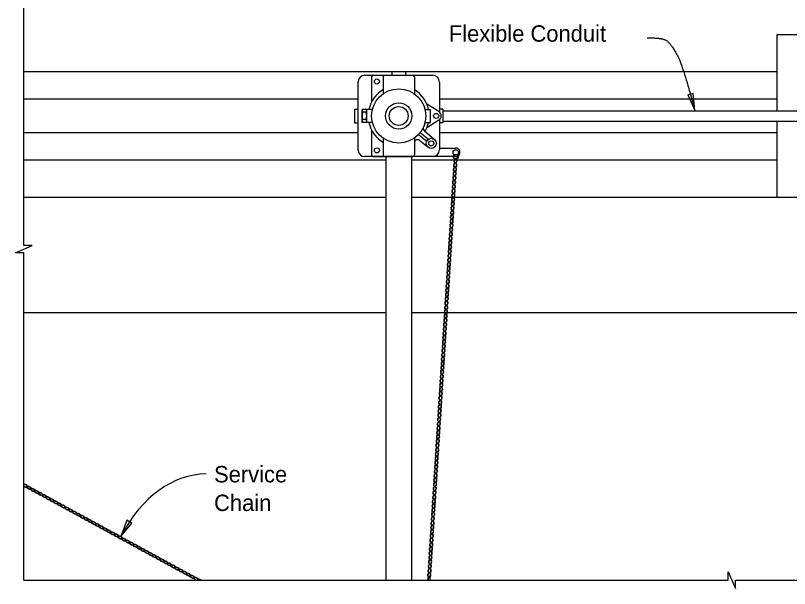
# Model space of a CAD drawing. Extents: x 83976.6 to 84012, y 72958.9 to 72975.6.
# Drawn here: x 83982.392 to 83987.152, y 72963.229 to 72966.752 of the extents above; entities that cross this region are included whole.
import ezdxf

# ---------------------------------------------------------------- set-up
doc = ezdxf.new("R2010")
doc.units = 0
for name, color, linetype in [('DSText', 7, 'Continuous'), ('DSTitle', 7, 'Continuous'), ('Patterning', 7, 'Continuous'), ('PlotBorder_dp', 7, 'Continuous'), ('SheetLines_dp', 7, 'Continuous'), ('SupstrConc', 7, 'Continuous')]:
    doc.layers.add(name, color=color, linetype=linetype)

msp = doc.modelspace()

# ---------------------------------------------------------------- linework, layer by layer
at = {"layer": 'DSText'}
for p, q in [((83984.7905, 72966.4049), (83984.7072, 72966.4049)), ((83984.7072, 72966.4049), (83984.7072, 72966.3841)), ((83984.7905, 72966.4049), (83984.7905, 72966.3841)), ((83984.5822, 72966.3737), (83984.5822, 72966.2199)), ((83984.5926, 72966.3841), (83984.8351, 72966.3841)), ((83984.6524, 72966.3737), (83984.6524, 72966.27)), ((83984.8455, 72966.3737), (83984.8455, 72966.2699)), ((83984.478, 72966.1757), (83984.478, 72966.0924)), ((83984.478, 72966.1757), (83984.4988, 72966.1757)), ((83984.587, 72966.1736), (83984.5235, 72966.1736)), ((83984.5235, 72966.0945), (83984.5235, 72966.1736)), ((83984.5529, 72966.0945), (83984.5529, 72966.1736)), ((83984.9108, 72966.1736), (83984.9449, 72966.1736)), ((83984.9958, 72966.1606), (83984.922, 72966.206)), ((83984.9449, 72966.0945), (83984.9449, 72966.1736)), ((83985.0197, 72966.1757), (83984.9989, 72966.1757)), ((83985.0197, 72966.1757), (83985.0197, 72966.0924)), ((83984.5482, 72966.1566), (83984.5282, 72966.1566)), ((83985.0197, 72966.1653), (83987.7448, 72966.1653)), ((83984.478, 72966.0924), (83984.4988, 72966.0924)), ((83984.587, 72966.0945), (83984.5235, 72966.0945)), ((83984.5482, 72966.1122), (83984.5282, 72966.1122)), ((83984.9108, 72966.0945), (83984.9449, 72966.0945)), ((83984.9958, 72966.1075), (83984.922, 72966.0621)), ((83985.0197, 72966.0924), (83984.9989, 72966.0924)), ((83985.0197, 72966.1028), (83987.7448, 72966.1028)), ((83984.5822, 72966.0482), (83984.5822, 72965.8945)), ((83984.8814, 72966.033), (83984.9313, 72965.9912)), ((83984.9069, 72966.0422), (83984.9695, 72965.9897)), ((83984.6524, 72965.9981), (83984.6524, 72965.8945)), ((83984.8455, 72965.9982), (83984.8455, 72965.8945)), ((83984.8714, 72966.021), (83984.9212, 72965.9792)), ((83984.8796, 72965.9836), (83984.9293, 72965.9419)), ((83984.5926, 72965.8841), (83984.8351, 72965.8841)), ((83984.6697, 72965.884), (83984.6697, 72963.2807)), ((83984.828, 72965.884), (83984.828, 72963.2807))]:
    msp.add_line(p, q, dxfattribs=at)
for points in [[(83984.5406, 72966.3841), (83984.9572, 72966.3841)], [(83984.4989, 72965.9258), (83984.4989, 72966.3424)], [(83984.9989, 72966.3424), (83984.9989, 72966.1588)], [(83984.9989, 72966.1094), (83984.9989, 72965.9258)], [(83984.9989, 72965.9362), (83985.0997, 72965.9362)], [(83985.0997, 72965.8841), (83984.5406, 72965.8841)]]:
    msp.add_lwpolyline(points, dxfattribs=at)
for centre, radius in [((83984.6148, 72966.3458), 0.0156), ((83984.7489, 72966.1341), 0.1667), ((83984.7489, 72966.1341), 0.081), ((83984.7489, 72966.1341), 0.0582), ((83984.9794, 72966.1341), 0.0156), ((83984.9494, 72965.9658), 0.0312), ((83984.9494, 72965.9658), 0.0156), ((83984.6148, 72965.9223), 0.0156), ((83985.0997, 72965.9101), 0.0168)]:
    msp.add_circle(centre, radius, dxfattribs=at)
for centre, radius, start, end in [((83984.5406, 72966.3424), 0.0417, 90, 180), ((83984.5926, 72966.3737), 0.0104, 90, 180), ((83984.6628, 72966.3737), 0.0104, 90, 180), ((83984.8351, 72966.3737), 0.0104, 0, 90), ((83984.9572, 72966.3424), 0.0417, 0, 90), ((83984.7489, 72966.1341), 0.1875, 120.9603, 167.8245), ((83984.7489, 72966.1341), 0.1875, 12.1755, 58.984), ((83984.5695, 72966.1769), 0.0461, 184.249, 206.2673), ((83984.5069, 72966.1769), 0.0461, 333.7327, 355.751), ((83984.579, 72966.1343), 0.0554, 156.4172, 203.5828), ((83984.4974, 72966.1343), 0.0554, 336.4172, 23.5828), ((83984.9794, 72966.1341), 0.0312, 301.564, 58.4266), ((83984.5695, 72966.0918), 0.0461, 153.7327, 175.751), ((83984.5069, 72966.0918), 0.0461, 4.249, 26.2673), ((83984.7489, 72966.1341), 0.1875, 192.1669, 239.0397), ((83984.7489, 72966.1341), 0.1875, 329.5786, 347.8331), ((83984.9203, 72966.0581), 0.0208, 156.1011, 230), ((83984.8663, 72965.9677), 0.0208, 50, 180), ((83985.0997, 72965.9101), 0.026, 269.9996, 90.0525), ((83984.5406, 72965.9258), 0.0417, 180, 270), ((83984.5926, 72965.8945), 0.0104, 180, 270), ((83984.6628, 72965.8945), 0.0104, 180, 270), ((83984.8351, 72965.8945), 0.0104, 270, 0), ((83984.9572, 72965.9258), 0.0417, 270, 0)]:
    msp.add_arc(centre, radius, start, end, dxfattribs=at)
at = {"layer": 'DSTitle'}
for radius in [0.0153, 0.0125]:
    msp.add_circle((83985.0997, 72965.8841), radius, dxfattribs=at)
for centre, major_axis, ratio in [((83985.0964, 72965.8318), (0.001, 0.0153), 0.530594), ((83985.0981, 72965.8583), (0.001, 0.0153), 0.530594), ((83985.0964, 72965.8318), (0.0008, 0.0133), 0.458548), ((83985.0981, 72965.8583), (0.0008, 0.0133), 0.458548), ((83985.0931, 72965.7788), (0.001, 0.0153), 0.530594), ((83985.0947, 72965.8053), (0.001, 0.0153), 0.530594), ((83985.0931, 72965.7788), (0.0008, 0.0133), 0.458548), ((83985.0947, 72965.8053), (0.0008, 0.0133), 0.458548), ((83985.0897, 72965.7258), (0.001, 0.0153), 0.530594), ((83985.0914, 72965.7523), (0.001, 0.0153), 0.530594), ((83985.0897, 72965.7258), (0.0008, 0.0133), 0.458548), ((83985.0914, 72965.7523), (0.0008, 0.0133), 0.458548), ((83985.088, 72965.6992), (0.001, 0.0153), 0.530594), ((83985.088, 72965.6992), (0.0008, 0.0133), 0.458548), ((83985.0847, 72965.6462), (0.001, 0.0153), 0.530594), ((83985.0863, 72965.6727), (0.001, 0.0153), 0.530594), ((83985.0847, 72965.6462), (0.0008, 0.0133), 0.458548), ((83985.0863, 72965.6727), (0.0008, 0.0133), 0.458548), ((83985.0813, 72965.5932), (0.001, 0.0153), 0.530594), ((83985.083, 72965.6197), (0.001, 0.0153), 0.530594), ((83985.0813, 72965.5932), (0.0008, 0.0133), 0.458548), ((83985.083, 72965.6197), (0.0008, 0.0133), 0.458548), ((83985.0779, 72965.5402), (0.001, 0.0153), 0.530594), ((83985.0796, 72965.5667), (0.001, 0.0153), 0.530594), ((83985.0779, 72965.5402), (0.0008, 0.0133), 0.458548), ((83985.0796, 72965.5667), (0.0008, 0.0133), 0.458548), ((83985.0746, 72965.4871), (0.001, 0.0153), 0.530594), ((83985.0763, 72965.5137), (0.001, 0.0153), 0.530594), ((83985.0746, 72965.4871), (0.0008, 0.0133), 0.458548), ((83985.0763, 72965.5137), (0.0008, 0.0133), 0.458548), ((83985.0729, 72965.4606), (0.001, 0.0153), 0.530594), ((83985.0729, 72965.4606), (0.0008, 0.0133), 0.458548), ((83985.0696, 72965.4076), (0.001, 0.0153), 0.530594), ((83985.0712, 72965.4341), (0.001, 0.0153), 0.530594), ((83985.0696, 72965.4076), (0.0008, 0.0133), 0.458548), ((83985.0712, 72965.4341), (0.0008, 0.0133), 0.458548), ((83985.0662, 72965.3546), (0.001, 0.0153), 0.530594), ((83985.0679, 72965.3811), (0.001, 0.0153), 0.530594), ((83985.0662, 72965.3546), (0.0008, 0.0133), 0.458548), ((83985.0679, 72965.3811), (0.0008, 0.0133), 0.458548), ((83985.0628, 72965.3015), (0.001, 0.0153), 0.530594), ((83985.0645, 72965.3281), (0.001, 0.0153), 0.530594), ((83985.0628, 72965.3015), (0.0008, 0.0133), 0.458548), ((83985.0645, 72965.3281), (0.0008, 0.0133), 0.458548), ((83985.0595, 72965.2485), (0.001, 0.0153), 0.530594), ((83985.0612, 72965.275), (0.001, 0.0153), 0.530594), ((83985.0595, 72965.2485), (0.0008, 0.0133), 0.458548), ((83985.0612, 72965.275), (0.0008, 0.0133), 0.458548), ((83985.0578, 72965.222), (0.001, 0.0153), 0.530594), ((83985.0578, 72965.222), (0.0008, 0.0133), 0.458548), ((83985.0544, 72965.169), (0.001, 0.0153), 0.530594), ((83985.0561, 72965.1955), (0.001, 0.0153), 0.530594), ((83985.0544, 72965.169), (0.0008, 0.0133), 0.458548), ((83985.0561, 72965.1955), (0.0008, 0.0133), 0.458548), ((83985.0511, 72965.1159), (0.001, 0.0153), 0.530594), ((83985.0528, 72965.1425), (0.001, 0.0153), 0.530594), ((83985.0511, 72965.1159), (0.0008, 0.0133), 0.458548), ((83985.0528, 72965.1425), (0.0008, 0.0133), 0.458548), ((83985.0477, 72965.0629), (0.001, 0.0153), 0.530594), ((83985.0494, 72965.0894), (0.001, 0.0153), 0.530594), ((83985.0477, 72965.0629), (0.0008, 0.0133), 0.458548), ((83985.0494, 72965.0894), (0.0008, 0.0133), 0.458548), ((83985.0444, 72965.0099), (0.001, 0.0153), 0.530594), ((83985.0461, 72965.0364), (0.001, 0.0153), 0.530594), ((83985.0444, 72965.0099), (0.0008, 0.0133), 0.458548), ((83985.0461, 72965.0364), (0.0008, 0.0133), 0.458548), ((83985.0427, 72964.9834), (0.001, 0.0153), 0.530594), ((83985.0427, 72964.9834), (0.0008, 0.0133), 0.458548), ((83985.0393, 72964.9304), (0.001, 0.0153), 0.530594), ((83985.041, 72964.9569), (0.001, 0.0153), 0.530594), ((83985.0393, 72964.9304), (0.0008, 0.0133), 0.458548), ((83985.041, 72964.9569), (0.0008, 0.0133), 0.458548), ((83985.036, 72964.8773), (0.001, 0.0153), 0.530594), ((83985.0377, 72964.9038), (0.001, 0.0153), 0.530594), ((83985.036, 72964.8773), (0.0008, 0.0133), 0.458548), ((83985.0377, 72964.9038), (0.0008, 0.0133), 0.458548), ((83985.0326, 72964.8243), (0.001, 0.0153), 0.530594), ((83985.0343, 72964.8508), (0.001, 0.0153), 0.530594), ((83985.0326, 72964.8243), (0.0008, 0.0133), 0.458548), ((83985.0343, 72964.8508), (0.0008, 0.0133), 0.458548), ((83985.0293, 72964.7713), (0.001, 0.0153), 0.530594), ((83985.0309, 72964.7978), (0.001, 0.0153), 0.530594), ((83985.0309, 72964.7978), (0.0008, 0.0133), 0.458548), ((83985.0276, 72964.7448), (0.001, 0.0153), 0.530594), ((83985.0276, 72964.7448), (0.0008, 0.0133), 0.458548), ((83985.0293, 72964.7713), (0.0008, 0.0133), 0.458548), ((83985.0242, 72964.6917), (0.001, 0.0153), 0.530594), ((83985.0259, 72964.7182), (0.001, 0.0153), 0.530594), ((83985.0242, 72964.6917), (0.0008, 0.0133), 0.458548), ((83985.0259, 72964.7182), (0.0008, 0.0133), 0.458548), ((83985.0209, 72964.6387), (0.001, 0.0153), 0.530594), ((83985.0226, 72964.6652), (0.001, 0.0153), 0.530594), ((83985.0209, 72964.6387), (0.0008, 0.0133), 0.458548), ((83985.0226, 72964.6652), (0.0008, 0.0133), 0.458548), ((83985.0175, 72964.5857), (0.001, 0.0153), 0.530594), ((83985.0192, 72964.6122), (0.001, 0.0153), 0.530594), ((83985.0175, 72964.5857), (0.0008, 0.0133), 0.458548), ((83985.0192, 72964.6122), (0.0008, 0.0133), 0.458548), ((83985.0142, 72964.5327), (0.001, 0.0153), 0.530594), ((83985.0158, 72964.5592), (0.001, 0.0153), 0.530594), ((83985.0158, 72964.5592), (0.0008, 0.0133), 0.458548), ((83985.0125, 72964.5061), (0.001, 0.0153), 0.530594), ((83985.0125, 72964.5061), (0.0008, 0.0133), 0.458548), ((83985.0142, 72964.5327), (0.0008, 0.0133), 0.458548), ((83985.0091, 72964.4531), (0.001, 0.0153), 0.530594), ((83985.0108, 72964.4796), (0.001, 0.0153), 0.530594), ((83985.0091, 72964.4531), (0.0008, 0.0133), 0.458548), ((83985.0108, 72964.4796), (0.0008, 0.0133), 0.458548), ((83985.0058, 72964.4001), (0.001, 0.0153), 0.530594), ((83985.0074, 72964.4266), (0.001, 0.0153), 0.530594), ((83985.0058, 72964.4001), (0.0008, 0.0133), 0.458548), ((83985.0074, 72964.4266), (0.0008, 0.0133), 0.458548), ((83985.0024, 72964.3471), (0.001, 0.0153), 0.530594), ((83985.0041, 72964.3736), (0.001, 0.0153), 0.530594), ((83985.0024, 72964.3471), (0.0008, 0.0133), 0.458548), ((83985.0041, 72964.3736), (0.0008, 0.0133), 0.458548), ((83984.9991, 72964.294), (0.001, 0.0153), 0.530594), ((83985.0007, 72964.3205), (0.001, 0.0153), 0.530594), ((83985.0007, 72964.3205), (0.0008, 0.0133), 0.458548), ((83984.9974, 72964.2675), (0.001, 0.0153), 0.530594), ((83984.9974, 72964.2675), (0.0008, 0.0133), 0.458548), ((83984.9991, 72964.294), (0.0008, 0.0133), 0.458548), ((83984.994, 72964.2145), (0.001, 0.0153), 0.530594), ((83984.9957, 72964.241), (0.001, 0.0153), 0.530594), ((83984.994, 72964.2145), (0.0008, 0.0133), 0.458548), ((83984.9957, 72964.241), (0.0008, 0.0133), 0.458548), ((83984.9907, 72964.1615), (0.001, 0.0153), 0.530594), ((83984.9923, 72964.188), (0.001, 0.0153), 0.530594), ((83984.9907, 72964.1615), (0.0008, 0.0133), 0.458548), ((83984.9923, 72964.188), (0.0008, 0.0133), 0.458548), ((83984.9873, 72964.1084), (0.001, 0.0153), 0.530594), ((83984.989, 72964.1349), (0.001, 0.0153), 0.530594), ((83984.9873, 72964.1084), (0.0008, 0.0133), 0.458548), ((83984.989, 72964.1349), (0.0008, 0.0133), 0.458548), ((83984.9856, 72964.0819), (0.001, 0.0153), 0.530594), ((83984.9856, 72964.0819), (0.0008, 0.0133), 0.458548), ((83984.9823, 72964.0289), (0.001, 0.0153), 0.530594), ((83984.9839, 72964.0554), (0.001, 0.0153), 0.530594), ((83984.9823, 72964.0289), (0.0008, 0.0133), 0.458548), ((83984.9839, 72964.0554), (0.0008, 0.0133), 0.458548), ((83984.9789, 72963.9759), (0.001, 0.0153), 0.530594), ((83984.9806, 72964.0024), (0.001, 0.0153), 0.530594), ((83984.9789, 72963.9759), (0.0008, 0.0133), 0.458548), ((83984.9806, 72964.0024), (0.0008, 0.0133), 0.458548), ((83984.9756, 72963.9228), (0.001, 0.0153), 0.530594), ((83984.9772, 72963.9494), (0.001, 0.0153), 0.530594), ((83984.9756, 72963.9228), (0.0008, 0.0133), 0.458548), ((83984.9772, 72963.9494), (0.0008, 0.0133), 0.458548), ((83984.9722, 72963.8698), (0.001, 0.0153), 0.530594), ((83984.9739, 72963.8963), (0.001, 0.0153), 0.530594), ((83984.9722, 72963.8698), (0.0008, 0.0133), 0.458548), ((83984.9739, 72963.8963), (0.0008, 0.0133), 0.458548), ((83982.4764, 72963.8479), (-0.0135, 0.0073), 0.530594), ((83982.4764, 72963.8479), (-0.0117, 0.0064), 0.458548), ((83982.4997, 72963.8352), (-0.0135, 0.0073), 0.530594), ((83982.4997, 72963.8352), (-0.0117, 0.0064), 0.458548), ((83982.5231, 72963.8225), (-0.0135, 0.0073), 0.530594), ((83984.9705, 72963.8433), (0.001, 0.0153), 0.530594), ((83984.9705, 72963.8433), (0.0008, 0.0133), 0.458548), ((83982.5231, 72963.8225), (-0.0117, 0.0064), 0.458548), ((83982.5464, 72963.8097), (-0.0135, 0.0073), 0.530594), ((83982.5464, 72963.8097), (-0.0117, 0.0064), 0.458548), ((83982.5697, 72963.797), (-0.0135, 0.0073), 0.530594), ((83982.5697, 72963.797), (-0.0117, 0.0064), 0.458548), ((83982.593, 72963.7843), (-0.0135, 0.0073), 0.530594), ((83982.593, 72963.7843), (-0.0117, 0.0064), 0.458548), ((83984.9672, 72963.7903), (0.001, 0.0153), 0.530594), ((83984.9688, 72963.8168), (0.001, 0.0153), 0.530594), ((83984.9672, 72963.7903), (0.0008, 0.0133), 0.458548), ((83984.9688, 72963.8168), (0.0008, 0.0133), 0.458548), ((83982.6164, 72963.7716), (-0.0135, 0.0073), 0.530594), ((83982.6164, 72963.7716), (-0.0117, 0.0064), 0.458548), ((83982.6397, 72963.7589), (-0.0135, 0.0073), 0.530594), ((83982.6397, 72963.7589), (-0.0117, 0.0064), 0.458548), ((83982.663, 72963.7461), (-0.0135, 0.0073), 0.530594), ((83982.663, 72963.7461), (-0.0117, 0.0064), 0.458548), ((83982.6863, 72963.7334), (-0.0135, 0.0073), 0.530594), ((83982.6863, 72963.7334), (-0.0117, 0.0064), 0.458548), ((83984.9638, 72963.7372), (0.001, 0.0153), 0.530594), ((83984.9655, 72963.7638), (0.001, 0.0153), 0.530594), ((83984.9638, 72963.7372), (0.0008, 0.0133), 0.458548), ((83984.9655, 72963.7638), (0.0008, 0.0133), 0.458548), ((83982.7096, 72963.7207), (-0.0135, 0.0073), 0.530594), ((83982.7096, 72963.7207), (-0.0117, 0.0064), 0.458548), ((83982.733, 72963.708), (-0.0135, 0.0073), 0.530594), ((83982.733, 72963.708), (-0.0117, 0.0064), 0.458548), ((83982.7563, 72963.6953), (-0.0135, 0.0073), 0.530594), ((83982.7563, 72963.6953), (-0.0117, 0.0064), 0.458548), ((83982.7796, 72963.6825), (-0.0135, 0.0073), 0.530594), ((83982.7796, 72963.6825), (-0.0117, 0.0064), 0.458548), ((83984.9604, 72963.6842), (0.001, 0.0153), 0.530594), ((83984.9621, 72963.7107), (0.001, 0.0153), 0.530594), ((83984.9604, 72963.6842), (0.0008, 0.0133), 0.458548), ((83984.9621, 72963.7107), (0.0008, 0.0133), 0.458548), ((83982.8029, 72963.6698), (-0.0135, 0.0073), 0.530594), ((83982.8029, 72963.6698), (-0.0117, 0.0064), 0.458548), ((83982.8263, 72963.6571), (-0.0135, 0.0073), 0.530594), ((83982.8263, 72963.6571), (-0.0117, 0.0064), 0.458548), ((83982.8496, 72963.6444), (-0.0135, 0.0073), 0.530594), ((83982.8496, 72963.6444), (-0.0117, 0.0064), 0.458548), ((83982.8729, 72963.6316), (-0.0135, 0.0073), 0.530594), ((83984.9571, 72963.6312), (0.001, 0.0153), 0.530594), ((83984.9588, 72963.6577), (0.001, 0.0153), 0.530594), ((83984.9571, 72963.6312), (0.0008, 0.0133), 0.458548), ((83984.9588, 72963.6577), (0.0008, 0.0133), 0.458548), ((83982.8729, 72963.6316), (-0.0117, 0.0064), 0.458548), ((83982.8962, 72963.6189), (-0.0135, 0.0073), 0.530594), ((83982.8962, 72963.6189), (-0.0117, 0.0064), 0.458548), ((83982.9196, 72963.6062), (-0.0135, 0.0073), 0.530594), ((83982.9196, 72963.6062), (-0.0117, 0.0064), 0.458548), ((83982.9429, 72963.5935), (-0.0135, 0.0073), 0.530594), ((83982.9429, 72963.5935), (-0.0117, 0.0064), 0.458548), ((83984.9554, 72963.6047), (0.001, 0.0153), 0.530594), ((83984.9554, 72963.6047), (0.0008, 0.0133), 0.458548), ((83982.9662, 72963.5808), (-0.0135, 0.0073), 0.530594), ((83982.9662, 72963.5808), (-0.0117, 0.0064), 0.458548), ((83982.9895, 72963.568), (-0.0135, 0.0073), 0.530594), ((83982.9895, 72963.568), (-0.0117, 0.0064), 0.458548), ((83983.0129, 72963.5553), (-0.0135, 0.0073), 0.530594), ((83983.0129, 72963.5553), (-0.0117, 0.0064), 0.458548), ((83983.0362, 72963.5426), (-0.0135, 0.0073), 0.530594), ((83983.0362, 72963.5426), (-0.0117, 0.0064), 0.458548), ((83984.9521, 72963.5517), (0.001, 0.0153), 0.530594), ((83984.9537, 72963.5782), (0.001, 0.0153), 0.530594), ((83984.9521, 72963.5517), (0.0008, 0.0133), 0.458548), ((83984.9537, 72963.5782), (0.0008, 0.0133), 0.458548), ((83983.0595, 72963.5299), (-0.0135, 0.0073), 0.530594), ((83983.0595, 72963.5299), (-0.0117, 0.0064), 0.458548), ((83983.0828, 72963.5172), (-0.0135, 0.0073), 0.530594), ((83983.0828, 72963.5172), (-0.0117, 0.0064), 0.458548), ((83983.1061, 72963.5044), (-0.0135, 0.0073), 0.530594), ((83983.1061, 72963.5044), (-0.0117, 0.0064), 0.458548), ((83983.1295, 72963.4917), (-0.0135, 0.0073), 0.530594), ((83983.1295, 72963.4917), (-0.0117, 0.0064), 0.458548), ((83984.9487, 72963.4986), (0.001, 0.0153), 0.530594), ((83984.9504, 72963.5251), (0.001, 0.0153), 0.530594), ((83984.9487, 72963.4986), (0.0008, 0.0133), 0.458548), ((83984.9504, 72963.5251), (0.0008, 0.0133), 0.458548), ((83983.1528, 72963.479), (-0.0135, 0.0073), 0.530594), ((83983.1528, 72963.479), (-0.0117, 0.0064), 0.458548), ((83983.1761, 72963.4663), (-0.0135, 0.0073), 0.530594), ((83983.1761, 72963.4663), (-0.0117, 0.0064), 0.458548), ((83983.1994, 72963.4536), (-0.0135, 0.0073), 0.530594), ((83983.1994, 72963.4536), (-0.0117, 0.0064), 0.458548), ((83984.9453, 72963.4456), (0.001, 0.0153), 0.530594), ((83984.947, 72963.4721), (0.001, 0.0153), 0.530594), ((83984.9453, 72963.4456), (0.0008, 0.0133), 0.458548), ((83984.947, 72963.4721), (0.0008, 0.0133), 0.458548), ((83983.2228, 72963.4408), (-0.0135, 0.0073), 0.530594), ((83983.2228, 72963.4408), (-0.0117, 0.0064), 0.458548), ((83983.2461, 72963.4281), (-0.0135, 0.0073), 0.530594), ((83983.2461, 72963.4281), (-0.0117, 0.0064), 0.458548), ((83983.2694, 72963.4154), (-0.0135, 0.0073), 0.530594), ((83983.2694, 72963.4154), (-0.0117, 0.0064), 0.458548), ((83983.2927, 72963.4027), (-0.0135, 0.0073), 0.530594), ((83983.2927, 72963.4027), (-0.0117, 0.0064), 0.458548), ((83984.942, 72963.3926), (0.001, 0.0153), 0.530594), ((83984.9437, 72963.4191), (0.001, 0.0153), 0.530594), ((83984.942, 72963.3926), (0.0008, 0.0133), 0.458548), ((83984.9437, 72963.4191), (0.0008, 0.0133), 0.458548), ((83983.3161, 72963.39), (-0.0135, 0.0073), 0.530594), ((83983.3161, 72963.39), (-0.0117, 0.0064), 0.458548), ((83983.3394, 72963.3772), (-0.0135, 0.0073), 0.530594), ((83983.3394, 72963.3772), (-0.0117, 0.0064), 0.458548), ((83983.3627, 72963.3645), (-0.0135, 0.0073), 0.530594), ((83983.3627, 72963.3645), (-0.0117, 0.0064), 0.458548), ((83983.386, 72963.3518), (-0.0135, 0.0073), 0.530594), ((83983.386, 72963.3518), (-0.0117, 0.0064), 0.458548), ((83984.9403, 72963.3661), (0.001, 0.0153), 0.530594), ((83984.9403, 72963.3661), (0.0008, 0.0133), 0.458548), ((83983.4093, 72963.3391), (-0.0135, 0.0073), 0.530594), ((83983.4093, 72963.3391), (-0.0117, 0.0064), 0.458548), ((83983.4327, 72963.3264), (-0.0135, 0.0073), 0.530594), ((83983.4327, 72963.3264), (-0.0117, 0.0064), 0.458548), ((83983.456, 72963.3136), (-0.0135, 0.0073), 0.530594), ((83983.456, 72963.3136), (-0.0117, 0.0064), 0.458548), ((83983.4793, 72963.3009), (-0.0135, 0.0073), 0.530594), ((83983.4793, 72963.3009), (-0.0117, 0.0064), 0.458548), ((83984.9369, 72963.313), (0.001, 0.0153), 0.530594), ((83984.9386, 72963.3395), (0.001, 0.0153), 0.530594), ((83984.9369, 72963.313), (0.0008, 0.0133), 0.458548), ((83984.9386, 72963.3395), (0.0008, 0.0133), 0.458548)]:
    msp.add_ellipse(centre, major_axis=major_axis, ratio=ratio, dxfattribs=at)
for centre, major_axis, ratio, start_param, end_param in [((83982.4531, 72963.8606), (-0.0135, 0.0073), 0.530594, 1.136711, 5.709865), ((83982.4531, 72963.8606), (-0.0117, 0.0064), 0.458548, 0.945695, 5.827628), ((83983.5026, 72963.2882), (-0.0135, 0.0073), 0.530594, 3.116324, 7.906784), ((83983.5026, 72963.2882), (-0.0117, 0.0064), 0.458548, 2.883494, 8.284687), ((83983.526, 72963.2755), (-0.0135, 0.0073), 0.530594, 4.474354, 6.548754), ((83983.526, 72963.2755), (-0.0117, 0.0064), 0.458548, 4.690379, 6.477803), ((83984.9353, 72963.2865), (0.001, 0.0153), 0.530594, 4.3543, 8.279228), ((83984.9353, 72963.2865), (0.0008, 0.0133), 0.458548, 4.285385, 8.339029)]:
    msp.add_ellipse(centre, major_axis=major_axis, ratio=ratio, start_param=start_param, end_param=end_param, dxfattribs=at)
at = {"layer": 'PlotBorder_dp'}
for p, q in [((83984.7072, 72966.4049), (83982.4439, 72966.4049)), ((83987.0765, 72966.4049), (83984.7905, 72966.4049)), ((83984.4989, 72966.2382), (83982.4439, 72966.2382)), ((83987.0765, 72966.2382), (83984.9989, 72966.2382)), ((83984.4989, 72966.0299), (83982.4439, 72966.0299)), ((83987.0765, 72966.0299), (83984.9989, 72966.0299)), ((83984.6697, 72965.8632), (83982.4439, 72965.8632)), ((83987.0765, 72965.8632), (83984.828, 72965.8632))]:
    msp.add_line(p, q, dxfattribs=at)
at = {"layer": 'SheetLines_dp'}
for points in [[(83982.4439, 72963.2807), (83982.4439, 72965.2923), (83982.3922, 72965.2923), (83982.4439, 72965.3148), (83982.4956, 72965.3373), (83982.4439, 72965.3373), (83982.4439, 72968.453)], [(83982.4439, 72963.2807), (83986.7743, 72963.2807), (83986.7743, 72963.3323), (83986.7968, 72963.2807), (83986.8193, 72963.229), (83986.8193, 72963.2807), (83990.5105, 72963.2807)]]:
    msp.add_lwpolyline(points, dxfattribs=at)
for points in [[(83986.569, 72966.1676), (83986.5602, 72966.2728), (83986.526, 72966.264)], [(83983.0401, 72963.5497), (83983.108, 72963.6306), (83983.0776, 72963.6485)]]:
    msp.add_lwpolyline(points, close=True, dxfattribs=at)
msp.add_ellipse((83983.5653, 72962.9033), major_axis=(0.001, -1.0298), ratio=0.654738, start_param=3.141603, end_param=4.033059, dxfattribs=at)
msp.add_open_spline([(83986.2768, 72966.6149), (83986.3672, 72966.6149), (83986.4189, 72966.5842), (83986.498, 72966.4437), (83986.569, 72966.1676)], degree=2, dxfattribs=at)
at = {"layer": 'SupstrConc'}
for p, q in [((83987.0765, 72966.6341), (83989.0765, 72966.6341)), ((83987.0765, 72966.1653), (83987.0765, 72966.6341)), ((83987.0765, 72965.6341), (83987.0765, 72966.1028)), ((83982.4439, 72965.6341), (83984.6697, 72965.6341)), ((83984.828, 72965.6341), (83990.5104, 72965.6341)), ((83982.4439, 72964.9258), (83984.6697, 72964.9258)), ((83984.828, 72964.9258), (83990.5104, 72964.9258))]:
    msp.add_line(p, q, dxfattribs=at)

# ---------------------------------------------------------------- texts
at = {"layer": 'Patterning'}
msp.add_text('Flexible Conduit', height=0.1008, dxfattribs=at).set_placement((83985.0573, 72966.5906))
at = {"layer": 'SheetLines_dp'}
for s, p in [('Service', (83983.6135, 72963.8813)), ('Chain', (83983.6135, 72963.7053))]:
    msp.add_text(s, height=0.1008, dxfattribs=at).set_placement(p)

doc.saveas('drawing.dxf')
